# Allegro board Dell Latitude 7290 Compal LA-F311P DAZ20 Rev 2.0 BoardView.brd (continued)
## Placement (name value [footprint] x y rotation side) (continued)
JUSB1  ACON_TCRA2-9U1U93  [ACON_TCRA2-9U1U93_9P-T]  284.36 75.4 270 bottom
JUSB2  ACON_TCRA2-9U1U93  [ACON_TCRA2-9U1U93_9P-T]  15.83 65.95 90 bottom
JUSBC1  JAE_DX07B024XJ1R1300~D  [JAE_DX07B024XJ1R1300_24P]  7.81 109.9 270 top
JUSH1  CVILU_CF5026FD0RK-05-NH  [CVILU_CF5026FD0RK-05-NH_26P-T]  233.45 59.02 180 bottom
JXDP1  JXT_FP270H-061G1AM  [JXT_FP270H-061G1AM_61P]  103.51 129.83 180 bottom
LA5  BLM15PX600SN1D_2P  [MURAT_BLM15PX600SN1D_2P]  250.45 55.95 180 top
LA6  BLM15PX330SN1D_2P  [MURAT_BLM15PX330SN1D_2P]  279.82 22.74 0 top
LA7  BLM15PX330SN1D_2P  [MURAT_BLM15PX330SN1D_2P]  279.82 24.78 0 top
LA8  BLM15PX330SN1D_2P  [MURAT_BLM15PX330SN1D_2P]  279.82 20.71 0 top
LA9  BLM15PX330SN1D_2P  [MURAT_BLM15PX330SN1D_2P]  279.82 18.68 0 top
LA10  BLM15PX330SN1D_2P  [MURAT_BLM15PX330SN1D_2P]  285 45.79 0 bottom
LA11  BLM15PX330SN1D_2P  [MURAT_BLM15PX330SN1D_2P]  285 44.59 0 bottom
LA12  BLM15PX600SN1D_2P  [MURAT_BLM15PX600SN1D_2P]  254.15 66.39 90 top
LA13  HCB2012VF-601T20_2P  [TAI-T_HCB2012KF-121T50_2P]  263.36 63 90 top
LA14  BLM15PX600SN1D_2P  [MURAT_BLM15PX600SN1D_2P]  261.71 65.56 90 top
LC1  BLM15GA750SN1D_2P  [MURAT_BLM15GA750SN1D_2P]  138.07 98.37 270 top
LC2  BLM15GA750SN1D_2P  [MURAT_BLM15GA750SN1D_2P]  129.18 122.43 270 bottom
LED3  LTW-C193DC-C_WHITE  [LED_LTW-C193DC-C_2P]  292.97 128.5 0 top
LI3  EXC24CQ900U_4P  [PANAS_EXC24CQ900U_4P]  23.54 61.94 180 bottom
LI7  EXC24CQ900U_4P  [PANAS_EXC24CQ900U_4P]  277.47 74.26 270 bottom
LI8  MCM1012B900F06BP_4P  [INPAQ_MCM1012B900F06BP_4P]  234.63 106.37 180 top
LI9  MCM1012B900F06BP_4P  [INPAQ_MCM1012B900F06BP_4P]  228.75 78.5 0 bottom
LI16  HCM1012GH900BP_4P  [INPAQ_HCM1012GH900BP_4P]  234.62 104.46 180 top
LI17  HCM1012GH900BP_4P  [INPAQ_HCM1012GH900BP_4P]  230.08 100.59 90 top
LL1  4.7UH +-20% MPB201210T-4R7M-NA2  [TAIYO_BRC2012T4R7MD_2P]  251.42 125.07 90 bottom
LT1  0.6UH_MND-04ABIR60M-XGL_20%  [MAG_MND-04ABIR60M-XGL_2P]  22.43 108.04 180 bottom
LT2  1UH_LQM18NN1R0K00D_10%  [MURAT_LQM18NN1R0K00D_2P]  35.19 88.91 0 bottom
LV1  BLM15PX221SN1D_2P  [MURAT_BLM15PX221SN1D_2P]  62.52 130.04 270 top
LV3  HCM1012GH900BP_4P  [TAIYO_MCF12102G900-T_4P-NPM]  18.21 77.5 180 bottom
LV6  HCM1012GH900BP_4P  [TAIYO_MCF12102G900-T_4P-NPM]  18.21 79.34 180 bottom
LV9  HCM1012GH900BP_4P  [TAIYO_MCF12102G900-T_4P-NPM]  18.21 83.02 180 bottom
LV12  HCM1012GH900BP_4P  [TAIYO_MCF12102G900-T_4P-NPM]  18.21 81.18 180 bottom
LV27  EXC24CQ900U_4P  [PANAS_EXC24CQ900U_4P]  52.6 121.61 0 top
LV31  12NH_LQG15HN12NJ02D_5%  [MURAT_LQG15HN12NJ02D_2P]  18.04 76.78 180 bottom
LV32  12NH_LQG15HN12NJ02D_5%  [MURAT_LQG15HN12NJ02D_2P]  18.04 77.67 180 bottom
LV33  12NH_LQG15HN12NJ02D_5%  [MURAT_LQG15HN12NJ02D_2P]  18.04 78.62 180 bottom
LV34  12NH_LQG15HN12NJ02D_5%  [MURAT_LQG15HN12NJ02D_2P]  18.04 79.51 180 bottom
LV35  12NH_LQG15HN12NJ02D_5%  [MURAT_LQG15HN12NJ02D_2P]  18.04 82.3 180 bottom
LV36  12NH_LQG15HN12NJ02D_5%  [MURAT_LQG15HN12NJ02D_2P]  18.04 83.19 180 bottom
LV37  12NH_LQG15HN12NJ02D_5%  [MURAT_LQG15HN12NJ02D_2P]  18.04 80.46 180 bottom
LV38  12NH_LQG15HN12NJ02D_5%  [MURAT_LQG15HN12NJ02D_2P]  18.04 81.35 180 bottom
LZ1  EXC24CQ900U_4P  [PANAS_EXC24CQ900U_4P]  56.17 121.28 90 top
NOREF  -  []  82.2 91.4 0 top
NOREF#2  -  []  290.6 26.3 0 top
NOREF#3  -  []  36.98 177.87 0 top
NOREF#4  -  []  82.2 113.55 0 top
NOREF#5  -  []  8.6 74.35 90 top
NOREF#6  -  []  286.4 68.2 0 top
NOREF#7  -  []  296.1 26.3 270 top
NOREF#8  -  []  207.1 64.27 0 top
NOREF#9  -  []  4.6 49.5 90 top
NOREF#10  -  []  279.9 13.95 90 top
NOREF#11  -  []  266.9 71.4 0 top
NOREF#12  -  []  5.55 98.7 90 top
NOREF#13  -  []  87.04 69.76 0 top
NOREF#14  -  []  275.9 102.5 0 top
NOREF#15  -  []  33.93 171.65 0 top
NOREF#16  -  []  5.55 115.6 90 top
NOREF#17  -  []  132.46 1.89 0 top
NOREF#18  -  []  114.83 70.48 0 top
NOREF#19  -  []  142 91.4 0 top
NOREF#20  -  []  278.53 3 0 top
NOREF#21  -  []  142 113.55 0 top
NOREF#22  -  []  103.92 72.82 0 top
NOREF#23  -  []  77.91 77.8 0 top
NOREF#24  -  []  126.11 70.5 180 bottom
NOREF#25  -  []  93.57 80.31 180 bottom
NOREF#26  -  []  125.02 40.97 180 bottom
NOREF#27  -  []  204.68 65.48 180 bottom
NOREF#28  -  []  78 132.55 180 bottom
PBATT1  DEREN_40-42251-01001RHF  [DEREN_40-42251-01001RHF_10P-T]  173.1 57.47 135 bottom
PC1  2200P_0402_50V7K  [C_0402]  167.6 56.77 90 top
PC2  2200P_0402_50V7K  [C_0402]  283.03 8.96 0 top
PC3  1U_0603_25V6K  [C_0603]  285.9 13.16 0 top
PC4  0.022U_0603_50V7K  [C_0603]  46.76 110.88 180 bottom
PC5  1000P_0603_50V7K  [C_0603]  40.98 118.95 270 bottom
PC6  0.022U_0603_50V7K  [C_0603]  48.06 120.36 180 bottom
PC7  0.1U_0603_25V7K  [C_0603]  42.25 118.95 270 bottom
PC8  10U_0805_25V6K  [C_0805]  44.31 114.69 180 bottom
PC9  0.1U_0402_10V7K  [C_0402]  55.19 115.86 0 top
PC10  2.2U 10V M X5R 0402  [C_0402]  63.59 118.24 90 bottom
PC11  1000P 50V K X7R 0603  [C_0603]  63.46 120.15 90 bottom
PC12  82P 50V +-5% NPO 0402  [C_0402]  39.13 57.63 0 top
PC100  100P 50V J NPO 0402  [C_0402]  154.39 73.66 90 top
PC102  0.1U_0603_25V7K  [C_0603]  157.52 71.57 90 bottom
PC103  100P 50V J NPO 0402  [C_0402]  153.37 73.42 180 top
PC104  10U_0603_25V6M  [C_0603]  153.06 72.09 180 bottom
PC105  10U_0603_25V6M  [C_0603]  153.06 72.09 180 top
PC106  22UF_0805_6.3V6M  [C_0805]  167.07 76.34 0 bottom
PC107  22UF_0805_6.3V6M  [C_0805]  167.07 76.34 0 top
PC108  22UF_0805_6.3V6M  [C_0805]  167.07 74.56 0 top
PC109  22UF_0805_6.3V6M  [C_0805]  167.07 74.56 0 bottom
PC110  22UF_0805_6.3V6M  [C_0805]  167.07 78.05 0 top
PC111  4.7U_0603_6.3V6K  [C_0603]  156.42 79.03 180 top
PC112  680P_0603_50V7K  [C_0603]  162.72 70.58 90 bottom
PC113  1000P_0402_50V7K  [C_0402]  154.75 78.86 90 bottom
PC114  0.1U_0603_25V7K  [C_0603]  187.6 50.87 90 bottom
PC115  0.1U_0402_25V6  [C_0402]  179 50.53 180 bottom
PC116  2200P_0402_50V7K  [C_0402]  178.31 51.5 180 bottom
PC117  10U_0805_25V6K  [C_0805]  179.93 51.77 90 top
PC118  10U_0805_25V6K  [C_0805]  179.93 51.77 90 bottom
PC119  4.7U_0603_6.3V6K  [C_0603]  186.14 57.22 0 top
PC120  22UF_0805_6.3V6M  [C_0805]  198.09 59.62 0 bottom
PC121  22UF_0805_6.3V6M  [C_0805]  197.76 52.74 270 top
PC122  22UF_0805_6.3V6M  [C_0805]  199.48 52.74 270 bottom
PC123  22UF_0805_6.3V6M  [C_0805]  197.76 52.74 270 bottom
PC124  22UF_0805_6.3V6M  [C_0805]  198.09 59.62 0 top
PC125  680P_0603_50V7K  [C_0603]  190.14 56.02 180 top
PC126  4.7U_0603_6.3V6K  [C_0603]  185.13 57.22 180 top
PC127  1000P_0402_50V7K  [C_0402]  184.86 58.93 90 bottom
PC128  4.7U_0603_6.3V6K  [C_0603]  153.71 78.8 90 bottom
PC129  22UF_0805_6.3V6M  [C_0805]  167.07 78.05 0 bottom
PC130  22UF_0805_6.3V6M  [C_0805]  199.48 52.74 270 top
PC133  1000P_0402_50V7K  [C_0402]  183.27 50.7 90 top
PC134  1000P_0402_50V7K  [C_0402]  178.62 50.77 270 top
PC135  1U_0402_25V6K  [C_0402]  179.53 50.77 270 top
PC136  1U_0402_25V6K  [C_0402]  149.5 71.13 0 bottom
PC137  1000P_0402_50V7K  [C_0402]  165.59 54.52 90 top
PC138  1000P_0402_50V7K  [C_0402]  163.89 51.01 270 top
PC139  1U_0402_25V6K  [C_0402]  162.93 50.99 270 top
PC140  1U_0402_25V6K  [C_0402]  161.9 51 270 top
PC141  100P_0402_50V8J  [C_0402]  168.14 73.19 180 top
PC142  100P_0402_50V8J  [C_0402]  196.15 50.61 90 bottom
PC143  100P_0402_50V8J  [C_0402]  181.24 53.52 270 top
PC200  10U_0805_25V6K  [C_0805]  66.67 74.05 0 top
PC201  10U_0805_25V6K  [C_0805]  66.67 74.05 0 bottom
PC202  100P 50V J NPO 0402  [C_0402]  67.13 75.39 0 bottom
PC203  100P 50V J NPO 0402  [C_0402]  67.13 75.39 0 top
PC204  680P_0603_50V7K  [C_0603]  67.24 70.18 90 top
PC205  0.1U_0603_16V7K  [C_0603]  63.02 67.19 0 bottom
PC206  1U_0402_6.3V6K  [C_0402]  64.49 69.51 180 bottom
PC207  2.2U_0402_6.3V6M  [C_0402]  64.93 69.16 180 top
PC208  330P_0402_50V7K  [C_0402]  63.96 70.81 0 top
PC209  22U_0603_6.3V6M  [C_0603]  70.54 69.23 0 top
PC210  22U_0603_6.3V6M  [C_0603]  68.92 57.41 270 bottom
PC211  22U_0603_6.3V6M  [C_0603]  67.71 57.41 270 bottom
PC212  22U_0603_6.3V6M  [C_0603]  66.5 57.44 270 bottom
PC213  22U_0603_6.3V6M  [C_0603]  68.92 57.41 270 top
PC214  10U_0603_6.3V6M  [C_0603]  67.71 57.41 270 top
PC216  100P 50V J NPO 0402  [C_0402]  70 57.17 270 bottom
PC217  100P_0402_50V8J  [C_0402]  70 57.17 270 top
PC218  1U_0402_10V6K  [C_0402]  70.67 72.53 0 top
PC219  22U_0603_6.3V6M  [C_0603]  70.55 68.01 0 top
PC221  0.1U_0402_10V7K  [C_0402]  70 75 90 top
PC222  0.1U_0402_10V7K  [C_0402]  72.67 75 90 top
PC223  10U_0603_6.3V6M  [C_0603]  66.5 57.44 270 top
PC224  100P_0402_50V8J  [C_0402]  66.22 76.93 270 top
PC301  0.1U_0402_25V6  [C_0402]  151.32 85.69 270 bottom
PC302  680P_0603_50V7K  [C_0603]  154.18 83.49 270 bottom
PC303  100P 50V J NPO 0402  [C_0402]  151.32 85.69 270 top
PC304  0.1U_0603_25V7K  [C_0603]  157.5 87.8 90 top
PC305  10U_0603_25V6M  [C_0603]  152.42 86.21 270 bottom
PC306  10U_0603_25V6M  [C_0603]  152.42 86.21 270 top
PC307  330P_0402_50V7K  [C_0402]  153.21 79.37 0 top
PC308  22U_0603_6.3V6M  [C_0603]  162.5 86.61 0 top
PC309  22U_0603_6.3V6M  [C_0603]  162.5 87.87 0 top
PC310  22U_0603_6.3V6M  [C_0603]  162.5 87.87 0 bottom
PC311  22U_0603_6.3V6M  [C_0603]  162.5 86.61 0 bottom
PC312  4.7U_0603_6.3V6K  [C_0603]  159.27 82.99 0 top
PC313  4.7U_0603_6.3V6K  [C_0603]  159.28 84.31 0 top
PC314  100P_0402_50V8J  [C_0402]  162.43 83.15 0 top
PC315  100P_0402_50V8J  [C_0402]  162.43 84.07 0 top
PC316  100P_0402_50V8J  [C_0402]  159.82 81.79 0 top
PC401  470P_0402_50V7K  [C_0402]  137.44 130.17 90 top
PC402  0.1U_0402_25V6  [C_0402]  142.84 128.14 90 top
PC403  10U_0603_10V6M  [C_0603]  144.68 130.19 90 bottom
PC404  10U_0603_10V6M  [C_0603]  144.68 130.19 90 top
PC406  22U_0603_6.3V6M  [C_0603]  135.85 127.85 0 top
PC407  22U_0603_6.3V6M  [C_0603]  135.85 127.85 0 bottom
PC408  0.1U_0402_25V6  [C_0402]  145.76 130.17 90 top
PC409  2200P_0402_50V7K  [C_0402]  145.76 130.17 90 bottom
PC410  470P_0402_50V7K  [C_0402]  138.15 132.74 90 top
PC411  0.1U_0402_25V6  [C_0402]  163.71 125.74 0 top
PC412  10U_0603_10V6M  [C_0603]  160.62 128.73 90 bottom
PC413  10U_0603_10V6M  [C_0603]  160.62 128.73 90 top
PC415  22U_0603_6.3V6M  [C_0603]  150.67 126.2 180 top
PC417  0.1U_0402_25V6  [C_0402]  161.69 128.65 90 bottom
PC418  2200P_0402_50V7K  [C_0402]  161.69 128.65 90 top
PC419  470P_0402_50V7K  [C_0402]  155.4 127.26 0 top
PC420  470P_0402_50V7K  [C_0402]  160.62 126.83 180 top
PC424  22U_0603_6.3V6M  [C_0603]  150.67 126.2 180 bottom
PC425  10U_0603_6.3V6M  [C_0603]  136.11 126.62 0 top
PC426  10U_0603_6.3V6M  [C_0603]  136.11 126.62 0 bottom
PC427  10U_0603_6.3V6M  [C_0603]  150.67 127.47 180 top
PC428  10U_0603_6.3V6M  [C_0603]  150.67 127.47 180 bottom
PC501  22U_0603_6.3V6M  [C_0603]  177.94 61.78 225 bottom
PC503  68P_0402_50V8J  [C_0402]  173.8 69.16 135 bottom
PC504  22U_0603_6.3V6M  [C_0603]  177.94 61.78 225 top
PC505  0.1U_0402_16V7K  [C_0402]  175.41 66.54 45 bottom
PC506  680P_0402_50V7K  [C_0402]  172.25 62.97 135 bottom
PC513  .1U_0402_16V7K  [C_0402]  150.26 56.58 90 top
PC514  4.7U_0603_6.3V6K  [C_0603]  151.43 62.24 180 top
PC515  0.01UF_0402_25V7K  [C_0402]  146.07 60.86 270 top
PC516  22U_0603_6.3V6M  [C_0603]  148.3 62.03 90 top
PC530  10U_0603_6.3V6M  [C_0603]  169.91 65.43 315 bottom
PC531  10U_0603_6.3V6M  [C_0603]  169.91 65.43 315 top
PC601  680P_0402_50V7K  [C_0402]  50.05 101.69 0 bottom
PC602  0.1U_0402_25V6  [C_0402]  43.38 92.53 180 bottom
PC603  1U_0603_10V6K  [C_0603]  42.73 96.59 180 bottom
PC604  0.22U_0603_25V7K  [C_0603]  42.73 97.8 180 bottom
PC605  47P_0402_50V8J~D  [C_0402]  45.97 94.58 270 bottom
PC606  100U_D_20VM_R55M  [C_D]  52.71 75.82 90 bottom
PC607  100U_D_20VM_R55M  [C_D]  57.17 80.99 0 bottom
PC608  10U 25V 0603 ZRB  [C_0603]  64.48 114.6 90 bottom
PC611  0.22U_0603_16V7K  [C_0603]  60.53 115.09 180 top
PC612  10U 25V 0603 ZRB  [C_0603]  64.48 114.6 90 top
PC613  330P_0402_50V7K  [C_0402]  45.39 92.04 270 bottom
PC614  2200P_0402_50V7K  [C_0402]  48.88 92.49 270 bottom
PC616  33P_0402_50V8J  [C_0402]  47.36 93.37 270 bottom
PC617  1200P_0402_50V7K  [C_0402]  49.15 87.8 270 top
PC618  330P_0402_50V7K  [C_0402]  47.17 89.82 0 bottom
PC619  0.01UF_0402_25V7K  [C_0402]  47.17 88.94 0 bottom
PC620  0.082U_0402_16V7K  [C_0402]  49.15 88.63 90 top
PC621  680P_0402_50V7K  [C_0402]  45.26 87.84 0 top
PC622  680P_0603_50V7K  [C_0603]  67.33 116.09 180 top
PC624  .022U 16V K X7R 0402  [C_0402]  50.92 88.42 90 bottom
PC625  330P_0402_50V7K  [C_0402]  50.67 92.82 90 bottom
PC626  0.047U_0402_25V7K  [C_0402]  50.03 88.42 90 bottom
PC627  2200P_0402_50V7K  [C_0402]  50.03 88.83 90 top
PC628  33P 50V J NPO 0402  [C_0402]  48 97.24 270 bottom
PC629  2200P_0402_50V7K  [C_0402]  50.62 96.35 0 bottom
PC630  2200P_0402_50V7K  [C_0402]  52.04 97.27 90 top
PC631  4700P 25V 0402  [C_0402]  46.21 96.34 0 bottom
PC632  1000P_0402_50V7K  [C_0402]  48.11 99.39 180 bottom
PC633  4700P 50V K X7R 0402  [C_0402]  49.14 99.75 180 top
PC635  0.022U_0402_16V7K  [C_0402]  50.97 87.95 0 top
PC636  33P_0402_50V8J  [C_0402]  48.87 94.88 0 bottom
PC637  0.033U 25V K X7R 0402  [C_0402]  49.14 100.62 180 top
PC638  0.022U_0402_16V7K  [C_0402]  51.98 91.01 90 bottom
PC639  1500P_0402_50V7K  [C_0402]  53.38 94.56 0 top
PC640  2200P_0402_50V7K  [C_0402]  51.65 100.51 0 bottom
PC641  .1U_0402_16V7K  [C_0402]  51.03 90.19 180 bottom
PC642  .022U 16V K X7R 0402  [C_0402]  53.27 97.24 180 bottom
PC643  330P_0402_50V7K  [C_0402]  49.78 97.24 270 bottom
PC644  .1U_0402_16V7K  [C_0402]  47.36 100.68 270 top
PC645  .1U_0402_16V7K  [C_0402]  51.54 97.24 180 bottom
PC646  0.047U_0402_25V7K  [C_0402]  52.47 98.14 180 bottom
PC647  680P_0402_50V7K  [C_0402]  55.17 94.58 270 top
PC649  0.01UF_0402_25V7K  [C_0402]  50.89 99.58 180 top
PC650  0.082U_0402_16V7K  [C_0402]  51.74 100.51 270 top
PC651  330P_0402_50V7K  [C_0402]  54.52 95.49 180 top
PC652  330P_0402_50V7K  [C_0402]  50.89 100.47 180 top
PC653  0.082U_0402_16V7K  [C_0402]  52.76 95.47 90 top
PC654  0.01UF_0402_25V7K  [C_0402]  54.52 96.38 180 top
PC655  0.22U_0603_16V7K  [C_0603]  55.47 103.44 90 bottom
PC656  10U 25V 0603 ZRB  [C_0603]  53.2 107.71 90 top
PC657  10U 25V 0603 ZRB  [C_0603]  54.2 106.55 180 top
PC658  10U 25V 0603 ZRB  [C_0603]  53.2 107.71 90 bottom
PC659  0.1U_0402_25V6K~D  [C_0402]  56.4 103.97 0 top
PC660  2200P_0402_50V7K  [C_0402]  56.4 104.86 0 top
PC661  1U_0402_10V6K  [C_0402]  61.53 107.58 90 bottom
PC662  680P_0603_50V7K  [C_0603]  58.39 111.01 180 top
PC663  0.22U_0603_16V7K  [C_0603]  55.6 84.03 90 bottom
PC664  10U 25V 0603 ZRB  [C_0603]  54.19 87.39 180 top
PC665  10U 25V 0603 ZRB  [C_0603]  54.19 86.18 180 top
PC668  1U_0402_10V6K  [C_0402]  61.59 88.53 90 bottom
PC669  1U_0402_10V6K  [C_0402]  59.17 85.32 180 bottom
PC670  680P_0603_50V7K  [C_0603]  61.97 86.14 180 top
PC671  0.22U_0603_16V7K  [C_0603]  53.83 100.24 0 bottom
PC672  10U 25V 0603 ZRB  [C_0603]  57.91 102.69 0 bottom
PC673  10U 25V 0603 ZRB  [C_0603]  57.91 101.43 0 top
PC674  10U 25V 0603 ZRB  [C_0603]  54.19 86.18 180 bottom
PC675  10U 25V 0603 ZRB  [C_0603]  54.19 87.39 180 bottom
PC676  1U_0402_10V6K  [C_0402]  58.64 104.63 180 bottom
PC677  1U_0402_10V6K  [C_0402]  55.08 96.84 90 bottom
PC678  680P_0603_50V7K  [C_0603]  63.13 95.12 180 top
PC679  0.1U 25V K X5R 0402  [C_0402]  57.03 101.22 180 bottom
PC680  0.1U 25V K X5R 0402  [C_0402]  54.24 107.67 90 bottom
PC681  0.1U 25V K X5R 0402  [C_0402]  54.19 88.39 90 bottom
PC682  10U 25V 0603 ZRB  [C_0603]  54.2 106.55 180 bottom
PC683  10U 25V 0603 ZRB  [C_0603]  57.91 101.43 0 bottom
PC684  10U 25V 0603 ZRB  [C_0603]  57.91 102.69 0 top
PC685  1U_0402_10V6K  [C_0402]  62.37 114.95 180 top
PC689  1000P_0402_50V7K  [C_0402]  62.15 61.21 0 top
PC690  1000P_0402_50V7K  [C_0402]  58.43 70.04 180 bottom
PC691  1U_0402_25V6K  [C_0402]  68.19 81.55 180 bottom
PC692  1U_0402_25V6K  [C_0402]  150.95 79.07 0 bottom
PC695  100P_0402_50V8J  [C_0402]  77.48 119.84 270 bottom
PC696  100P_0402_50V8J  [C_0402]  68.65 110.05 0 top
PC697  1U_0402_10V6K  [C_0402]  58.34 93.81 0 bottom
PC700  12P 50V J NPO 0402  [C_0402]  61.17 104.33 180 top
PC701  68P 50V J NPO 0402  [C_0402]  61.14 105.23 180 top
PC702  100P_0402_50V8J  [C_0402]  60.8 101.23 0 bottom
PC703  100P_0402_50V8J  [C_0402]  72.85 89.63 270 bottom
PC902  0.1U_0402_25V6  [C_0402]  48 79.1 0 top
PC903  2200P_0402_50V7K  [C_0402]  48 79.1 0 bottom
PC904  10U 25V K X6S 0805  [C_0805]  46.21 77.35 180 bottom
PC905  10U 25V K X6S 0805  [C_0805]  46.21 79.07 180 bottom
PC906  10U 25V K X6S 0805  [C_0805]  46.21 79.07 180 top
PC909  15U_B2_25VM_R100M  [C_B2]  46.75 74.76 0 bottom
PC911  10U 25V K X6S 0805  [C_0805]  46.21 77.35 180 top
PC913  10U_0805_25V6K  [C_0805]  58.95 76.3 180 bottom
PC914  10U_0805_25V6K  [C_0805]  58.94 74.6 180 top
PC915  10U_0805_25V6K  [C_0805]  58.95 76.3 180 top
PC916  10U_0805_25V6K  [C_0805]  58.94 74.6 180 bottom
PC921  15U_B2_25VM_R100M  [C_B2]  58.16 72.09 0 bottom
PC925  4.7U 6.3V M X5R 0402  [C_0402]  55.71 61.02 90 bottom
PC926  1U 25V K X5R 0402  [C_0402]  55.51 59.68 270 bottom
PC927  1U 25V K X5R 0402  [C_0402]  56.45 59.12 0 bottom
PC928  0.1U_0402_25V6  [C_0402]  58.89 77.6 180 top
PC929  2200P_0402_50V7K  [C_0402]  58.89 77.6 180 bottom
PC930  0.22U_0603_25V7K  [C_0603]  58.25 62.62 270 top
PC931  1U_0603_25V6  [C_0603]  54.44 58.3 90 bottom
PC932  1U_0402_6.3V6K  [C_0402]  58.76 57.91 90 bottom
PC933  1U_0402_6.3V6K  [C_0402]  53.85 57.34 0 bottom
PC934  0.22U_0603_25V7K  [C_0603]  62.19 56.84 180 top
PC935  10U_0805_25V6K  [C_0805]  176.14 51.79 270 bottom
PC936  10U_0805_25V6K  [C_0805]  176.14 51.79 270 top
PC937  4700P_0402_25V7K  [C_0402]  59.27 52.07 90 top
PC938  10P_0402_50V8J  [C_0402]  53.85 54.67 0 bottom
PC939  0.1U_0402_25V6  [C_0402]  59.18 57.03 180 bottom
PC940  680P_0603_50V7K  [C_0603]  40.54 70.18 90 top
PC941  680P_0603_50V7K  [C_0603]  52.41 65.1 90 top
PC942  1U 25V K X5R 0402  [C_0402]  59.16 56.14 180 bottom
PC943  560P_0402_50V7K  [C_0402]  56.12 54.35 90 bottom
PC944  0.01UF 25V K X7R 0402  [C_0402]  54.75 52.14 0 bottom
PC945  1U 25V K X5R 0402  [C_0402]  60.48 54.93 90 bottom
PC946  0.22U 25V K X5R 0402  [C_0402]  58.95 54.35 90 bottom
PC947  0.1U_0402_25V6  [C_0402]  57.01 54.35 90 bottom
PC949  0.1U_0402_10V7K  [C_0402]  45.19 56.46 180 bottom
PC950  0.1U_0402_25V6  [C_0402]  58.06 55.27 270 bottom
PC951  10U_0805_25VAK  [C_0805]  47.45 77.81 0 bottom
PC952  10U_0805_25VAK  [C_0805]  47.45 77.81 0 top
PC955  0.1U 25V K X5R 0402  [C_0402]  50.53 63.03 0 top
PC956  1000P_0402_50V7K  [C_0402]  62.27 63.12 0 top
PC957  1000P_0402_50V7K  [C_0402]  62.25 62.23 0 top
PC958  1U_0402_25V6K  [C_0402]  62.28 63.99 0 top
PC959  1U_0402_25V6K  [C_0402]  62.27 64.88 0 top
PC960  100P_0402_50V8J  [C_0402]  64.06 60.64 0 top
PC961  100P_0402_50V8J  [C_0402]  64.03 58.72 0 top
PC962  100P_0402_50V8J  [C_0402]  64.07 59.7 0 top
PC1001  22U_0603_6.3V6M  [C_0603]  111.34 101.88 270 top
PC1002  22U_0603_6.3V6M  [C_0603]  108.93 101.89 270 top
PC1003  22U_0603_6.3V6M  [C_0603]  107.75 104.24 270 top
PC1004  22U_0603_6.3V6M  [C_0603]  112.53 101.86 270 top
PC1005  22U_0603_6.3V6M  [C_0603]  73.81 110.82 90 bottom
PC1006  22U_0603_6.3V6M  [C_0603]  83.01 105.92 270 bottom
PC1007  22U_0603_6.3V6M  [C_0603]  110.15 106.59 270 top
PC1008  22U_0603_6.3V6M  [C_0603]  73.81 110.82 90 top
PC1009  22U_0603_6.3V6M  [C_0603]  83.02 108.6 270 bottom
PC1010  22U_0603_6.3V6M  [C_0603]  81.81 108.6 270 bottom
PC1011  22U_0603_6.3V6M  [C_0603]  87.84 105.74 270 top
PC1012  22U_0603_6.3V6M  [C_0603]  75.02 110.83 90 top
PC1013  22U_0603_6.3V6M  [C_0603]  84.22 105.74 270 top
PC1014  22U_0603_6.3V6M  [C_0603]  98.9 106.85 270 top
PC1015  22U_0603_6.3V6M  [C_0603]  100.14 106.84 270 top
PC1016  22U_0603_6.3V6M  [C_0603]  86.7 103.56 270 bottom
PC1017  22U_0603_6.3V6M  [C_0603]  84.21 103.54 270 bottom
PC1018  22U_0603_6.3V6M  [C_0603]  81.78 103.29 270 bottom
PC1019  22U_0603_6.3V6M  [C_0603]  99.03 104.5 270 top
PC1020  22U_0603_6.3V6M  [C_0603]  100.25 104.5 270 top
PC1021  22U_0603_6.3V6M  [C_0603]  82.99 103.28 270 bottom
PC1022  22U_0603_6.3V6M  [C_0603]  85.5 103.55 270 bottom
PC1023  22U_0603_6.3V6M  [C_0603]  81.77 100.53 270 bottom
PC1024  22U_0603_6.3V6M  [C_0603]  83.01 100.52 270 bottom
PC1025  22U_0603_6.3V6M  [C_0603]  98.9 102.07 270 top
PC1026  22U_0603_6.3V6M  [C_0603]  100.09 102.07 270 top
PC1027  22U_0603_6.3V6M  [C_0603]  84.29 102.18 270 top
PC1028  22U_0603_6.3V6M  [C_0603]  84.29 99.39 270 top
PC1029  22U_0603_6.3V6M  [C_0603]  90.17 95.56 90 top
PC1030  1U_0201_6.3V6M  [C_0201]  113.88 106.09 0 top
PC1031  1U_0201_6.3V6M  [C_0201]  106.84 105.19 180 top
PC1032  1U_0201_6.3V6M  [C_0201]  113.88 102.59 0 top
PC1033  1U_0201_6.3V6M  [C_0201]  113.88 103.17 0 top
PC1034  1U_0201_6.3V6M  [C_0201]  113.88 103.76 0 top
PC1035  1U_0201_6.3V6M  [C_0201]  113.88 104.34 0 top
PC1036  1U_0201_6.3V6M  [C_0201]  113.88 104.93 0 top
PC1037  1U_0201_6.3V6M  [C_0201]  113.88 105.51 0 top
PC1038  1U_0201_6.3V6M  [C_0201]  106.83 102.4 180 top
PC1039  1U_0201_6.3V6M  [C_0201]  106.84 104.63 180 top
PC1040  1U_0201_6.3V6M  [C_0201]  98.54 109 0 top
PC1041  1U_0201_6.3V6M  [C_0201]  97.81 108.56 90 top
PC1042  1U_0201_6.3V6M  [C_0201]  101.51 108.88 180 top
PC1043  1U_0201_6.3V6M  [C_0201]  92.19 104.66 90 top
PC1044  1U_0201_6.3V6M  [C_0201]  92.19 102.84 90 top
PC1045  1U_0201_6.3V6M  [C_0201]  91.46 101.92 90 top
PC1046  1U_0201_6.3V6M  [C_0201]  96.04 106.52 90 top
PC1047  1U_0201_6.3V6M  [C_0201]  93.43 104.62 90 top
PC1048  1U_0201_6.3V6M  [C_0201]  93.52 103.52 270 top
PC1049  1U_0201_6.3V6M  [C_0201]  101.4 97.2 90 top
PC1050  1U_0201_6.3V6M  [C_0201]  114.49 109.09 180 top
PC1051  1U_0201_6.3V6M  [C_0201]  112.7 108.98 0 top
PC1052  1U_0201_6.3V6M  [C_0201]  110.87 108.98 180 top
PC1053  1U_0201_6.3V6M  [C_0201]  109.08 108.98 0 top
PC1055  1U_0201_6.3V6M  [C_0201]  93.19 101.41 0 top
PC1056  1U_0201_6.3V6M  [C_0201]  94.76 106.47 90 top
PC1057  22U_0603_6.3V6M  [C_0603]  118.04 99.81 180 top
PC1058  22U_0603_6.3V6M  [C_0603]  119.01 99.81 0 top
PC1059  22U_0603_6.3V6M  [C_0603]  117.22 107.13 180 top
PC1060  22U_0603_6.3V6M  [C_0603]  117.75 104.63 90 top
PC1061  22U_0603_6.3V6M  [C_0603]  76.22 110.82 90 bottom
PC1062  330U_D3_2VM_R6M  [C_D3]  73.58 107.07 180 top
PC1063  330U_D3_2VM_R6M  [C_D3]  73.3 95.01 270 top
PC1064  22U_0603_6.3V6M  [C_0603]  89.05 105.74 270 top
PC1065  22U_0603_6.3V6M  [C_0603]  90.28 105.74 270 top
PC1066  22U_0603_6.3V6M  [C_0603]  111.34 104.21 270 top
PC1067  22U_0603_6.3V6M  [C_0603]  108.94 106.59 270 top
PC1068  22U_0603_6.3V6M  [C_0603]  110.15 104.24 270 top
PC1069  22U_0603_6.3V6M  [C_0603]  80.61 105.74 270 bottom
PC1070  22U_0603_6.3V6M  [C_0603]  81.81 105.74 270 bottom
PC1071  22U_0603_6.3V6M  [C_0603]  80.61 108.6 270 bottom
PC1072  22U_0603_6.3V6M  [C_0603]  85.43 105.74 270 top
PC1073  22U_0603_6.3V6M  [C_0603]  108.94 104.24 270 top
PC1074  22U_0603_6.3V6M  [C_0603]  75.02 110.83 90 bottom
PC1075  22U_0603_6.3V6M  [C_0603]  86.64 105.74 270 top
PC1076  22U_0603_6.3V6M  [C_0603]  112.53 104.2 270 top
PC1077  22U_0603_6.3V6M  [C_0603]  111.34 106.59 270 top
PC1078  22U_0603_6.3V6M  [C_0603]  107.75 106.58 270 top
PC1079  22U_0603_6.3V6M  [C_0603]  84.21 105.92 270 bottom
PC1080  22U_0603_6.3V6M  [C_0603]  107.73 101.89 270 top
PC1081  22U_0603_6.3V6M  [C_0603]  110.13 101.89 270 top
PC1082  22U_0603_6.3V6M  [C_0603]  112.53 106.59 270 top
PC1083  1U_0201_6.3V6M  [C_0201]  106.83 104.07 180 top
PC1084  1U_0201_6.3V6M  [C_0201]  111.49 108.98 0 top
PC1085  1U_0201_6.3V6M  [C_0201]  111.39 110.12 0 top
PC1086  1U_0201_6.3V6M  [C_0201]  106.83 103.52 180 top
PC1087  1U_0201_6.3V6M  [C_0201]  113.49 97.77 270 top
PC1088  1U_0201_6.3V6M  [C_0201]  113.52 99.08 180 top
PC1089  1U_0201_6.3V6M  [C_0201]  112.89 97.77 270 top
PC1090  1U_0201_6.3V6M  [C_0201]  113.89 106.68 0 top
PC1091  1U_0201_6.3V6M  [C_0201]  113.88 107.27 0 top
PC1092  1U_0201_6.3V6M  [C_0201]  106.83 102.96 180 top
PC1093  1U_0201_6.3V6M  [C_0201]  113.88 102 0 top
PC1094  1U_0201_6.3V6M  [C_0201]  113.88 101.42 0 top
PC1095  1U_0201_6.3V6M  [C_0201]  113.88 100.84 0 top
PC1096  1U_0201_6.3V6M  [C_0201]  113.5 100.26 0 top
PC1097  1U_0201_6.3V6M  [C_0201]  111.68 99.67 0 top
PC1098  1U_0201_6.3V6M  [C_0201]  109.98 99.68 0 top
PC1099  1U_0201_6.3V6M  [C_0201]  106.83 101.28 180 top
PC1127  330U_D2_2.5VM_R9M  [C_D2]  74.51 108.3 270 bottom
PC1128  330U_D2_2.5VM_R9M  [C_D2]  74.51 98.27 270 bottom
PC1129  22U_0603_6.3V6M  [C_0603]  90.32 99.39 270 top
PC1130  22U_0603_6.3V6M  [C_0603]  90.32 102.18 270 top
PC1131  22U_0603_6.3V6M  [C_0603]  89.11 102.18 270 top
PC1132  22U_0603_6.3V6M  [C_0603]  89.11 99.4 270 top
PC1133  22U_0603_6.3V6M  [C_0603]  87.91 102.18 270 top
PC1134  22U_0603_6.3V6M  [C_0603]  87.92 99.41 270 top
PC1135  22U_0603_6.3V6M  [C_0603]  86.7 102.18 270 top
PC1136  22U_0603_6.3V6M  [C_0603]  86.7 99.39 270 top
PC1137  22U_0603_6.3V6M  [C_0603]  85.49 102.18 270 top
PC1138  22U_0603_6.3V6M  [C_0603]  85.49 99.39 270 top
PC1139  22U_0603_6.3V6M  [C_0603]  117.4 103.55 180 top
PC1140  22U_0603_6.3V6M  [C_0603]  116.55 104.66 90 top
PC1141  22U_0603_6.3V6M  [C_0603]  74.38 118.76 90 top
PC1142  22U_0603_6.3V6M  [C_0603]  75.7 118.8 90 bottom
PC1143  22U_0603_6.3V6M  [C_0603]  73.08 118.77 90 top
PC1144  22U_0603_6.3V6M  [C_0603]  74.38 118.76 90 bottom
PC1145  22U_0603_6.3V6M  [C_0603]  75.7 118.8 90 top
PC1146  22U_0603_6.3V6M  [C_0603]  73.08 118.77 90 bottom
PC1147  1U_0201_6.3V6M  [C_0201]  116.31 110.17 180 top
PC1148  1U_0201_6.3V6M  [C_0201]  118.39 107.62 270 top
PC1149  1U_0201_6.3V6M  [C_0201]  115.65 106.14 180 top
PC1150  1U_0201_6.3V6M  [C_0201]  115.65 105.57 180 top
PC1151  1U_0201_6.3V6M  [C_0201]  115.65 105 180 top
PC1152  1U_0201_6.3V6M  [C_0201]  118.48 103.49 0 top
PC1153  1U_0201_6.3V6M  [C_0201]  118.48 102.91 0 top
PC1201  0.01U_0402_25V7K~D  [C_0402]  36.47 58.7 270 bottom
PC1202  0.47U 25V K X7R 0603  [C_0603]  46.84 103.58 270 top
PC1203  1500P_0402_50V7K  [C_0402]  47.39 109.62 270 top
PC1204  0.1U_0402_10V7K  [C_0402]  35.06 63.7 0 bottom
PC1205  100P_0402_50V8J~D  [C_0402]  39.66 53.35 180 top
PC1206  220P_0402_50V8J~D  [C_0402]  40.97 55.13 0 top
PC1207  1200P_0402_50V7K  [C_0402]  41.87 56.92 270 top
PC1208  1000P_0402_50V7K  [C_0402]  22.95 112.98 0 top
PC1210  1500P_0402_50V7K  [C_0402]  31.14 120.93 270 top
PC1211  100P_0402_50V8J  [C_0402]  36.59 55.13 0 top
PC1212  100P_0402_50V8J  [C_0402]  36.59 56.91 0 top
PC1213  1200P_0402_50V7K  [C_0402]  35.14 56.7 90 top
PC1214  0.01UF_0402_25V7K  [C_0402]  28.03 124.2 90 top
PC1216  100P_0402_50V8J  [C_0402]  26.15 112.98 180 top
PC1217  1500P_0402_50V7K  [C_0402]  248.94 97.22 90 top
PC1321  220U_D7_2VM_R4.5M  [C_D7]  68.68 102.28 180 top
PC1322  22U_0603_6.3V6M  [C_0603]  103.96 102.41 0 top
PC1323  22U_0603_6.3V6M  [C_0603]  103.96 103.62 0 top
PC1324  22U_0603_6.3V6M  [C_0603]  103.96 104.81 0 top
PC1325  22U_0603_6.3V6M  [C_0603]  102.74 103.62 180 top
PC1326  22U_0603_6.3V6M  [C_0603]  102.74 102.42 180 top
PC1327  22U_0603_6.3V6M  [C_0603]  102.74 104.82 180 top
PC1328  1U_0201_6.3V6M  [C_0201]  94.09 106.43 90 top
PC1329  1U_0201_6.3V6M  [C_0201]  97.73 106.97 270 top
PC1330  1U_0201_6.3V6M  [C_0201]  104.63 96.15 0 top
PC1331  1U_0201_6.3V6M  [C_0201]  103.53 95.51 180 top
PC1332  1U_0201_6.3V6M  [C_0201]  104.63 95.51 0 top
PC1333  1U_0201_6.3V6M  [C_0201]  103.53 96.13 180 top
PC1334  1U_0201_6.3V6M  [C_0201]  105.27 97.29 0 top
PD1  -  [TVNST52302AB0_SOT523-3]  166.79 64.51 45 top
PD2  -  [TVNST52302AB0_SOT523-3]  165.33 63.05 45 top
PD3  BAS40CW SOT-323  [DB3J315E0L_SMINI3-F2-B3]  285.9 11.88 0 top
PD4  -  [PESD5V0U2BT_SOT23-3]  39.66 127.29 180 top
PD5  S SCH DIO 5A 100V 15UA 0.88V TO227-3  [PDS5100H-13_POWERDI5-3]  51.08 114.14 90 bottom
PD6  -  [DFLS160-7_POWERDI123-2]  45.63 118.34 45 top
PD901  SDMK0340L-7-F_SOD323-2~D  [SDMK0340L-7-F_SOD323-2]  48.91 57.54 180 bottom
PD903  -  [RB520SM-30T2R_EMD2-2]  48.91 59.26 180 bottom
PD904  SDMK0340L-7-F_SOD323-2~D  [SDMK0340L-7-F_SOD323-2]  48.91 60.97 180 bottom
PD905  -  [BAT54CW_SOT323-3]  42.51 57.61 0 bottom
PD906  SMF4L22A SOD123FL-2  [SMF22A-SOD123FL-2-S]  48.17 82.62 0 top
PD1202  S SCH DIO 5A 100V 15UA 0.88V TO227-3  [PDS5100H-13_POWERDI5-3]  49.36 107.63 270 bottom
PD1205  -  [SDMK0340L-7-F_SOD323-2]  35.14 54.25 90 bottom
PD1801  BAT54CW-7-F SOT-323  [BAT54CW_SOT323-3]  37.55 58.3 270 bottom
PH601  470K_0402_5%_B25/50 4700K  [R_0402]  54.71 93.8 0 bottom
PH602  10K_0402_5%_B25/50 4250K  [R_0402]  67.27 103.2 180 bottom
PH603  470K_0402_5%_B25/50 4700K  [R_0402]  49.75 91.08 0 bottom
PH604  10KB_0402_5%  [R_0402]  71.79 119.64 270 bottom
PH605  10K_0402_5%_B25/50 4250K  [R_0402]  68.49 85.73 0 bottom
PJP1  PAD-OPEN1X1M  [JUMP_43X39]  124.03 126.12 0 top
PJP2  PAD-OPEN1X1M  [JUMP_43X39]  120.42 125.41 90 top
PJP3  PAD-OPEN1X3M  [JUMP_43X118]  139.91 122.87 270 bottom
PJP4  PAD-OPEN1X1M  [JUMP_43X39]  146.47 83.13 180 top
PJP5  -  [JUMP_43X79]  22.76 110.37 0 top
PJP6  PAD-OPEN1X1M  [JUMP_43X39]  20.47 107.58 90 top
PJP7  PAD-OPEN1X1M  [JUMP_43X39]  34.3 72.97 0 bottom
PJP8  PAD-OPEN 1X3M  [JUMP_43X118]  24.52 85.9 0 top
PJP13  PAD-OPEN1X1M  [JUMP_43X39]  65.04 127.2 0 top
PJP14  PAD-OPEN1X2M  [JUMP_43X79]  271.76 73.35 0 top
PJP15  PAD-OPEN1X1M  [JUMP_43X39]  247.99 67.4 270 top
PJP16  PAD-OPEN1X1M  [JUMP_43X39]  246.21 60.16 270 top
PJP17  PAD-OPEN1X2M  [JUMP_43X79]  243.17 59.68 270 top
PJP18  PAD-OPEN1X1M  [JUMP_43X39]  245.77 66.48 90 top
PJP19  PAD-OPEN1X1M  [JUMP_43X39]  265.89 57.54 0 top
PJP20  PAD-OPEN1X1M  [JUMP_43X39]  262.37 87.12 90 top
PJP21  PAD-OPEN1X1M  [JUMP_43X39]  259.99 87.12 90 top
PJP22  PAD-OPEN1X1M  [JUMP_43X39]  251.46 76.13 90 top
PJP31  PAD-OPEN1X3M  [JUMP_43X118]  27.65 52.42 90 bottom
PJP35  PAD-OPEN1X1M  [JUMP_43X39]  206.58 56.4 0 top
PJP36  PAD-OPEN1X2M  [JUMP_43X79]  249.39 108.38 270 top
PJP37  PAD-OPEN1X1M  [JUMP_43X39]  248.7 113.36 180 top
PJP38  PAD-OPEN1X1M  [JUMP_43X39]  149.68 65.42 180 top
PJP39  PAD-OPEN1X3M  [JUMP_43X118]  153 65.31 90 top
PJP40  PAD-OPEN1X2M  [JUMP_43X79]  276.1 86.05 180 top
PJP41  PAD-OPEN1X3M  [JUMP_43X118]  276.67 95.9 180 top
PJP42  PAD-OPEN1X1M  [JUMP_43X39]  211.59 51.45 0 top
PJP100  PAD-OPEN 1X2M~D  [JUMP_43X79]  153.12 68.61 90 bottom
PJP101  PAD-OPEN 1X2M~D  [JUMP_43X79]  182.9 50.77 90 bottom
PJP102  -  [JUMP_43X118]  167.84 72.1 270 bottom
PJP103  -  [JUMP_43X118]  198.62 56.03 0 bottom
PJP200  -  [JUMP_43X118]  71.8 58.43 0 top
PJP201  -  [JUMP_43X39]  70.84 65.91 0 top
PJP202  PAD-OPEN 1X2M~D  [JUMP_43X79]  63.48 75.19 0 top
PJP301  PAD-OPEN 1X2M~D  [JUMP_43X79]  150.81 82.09 90 top
PJP302  -  [JUMP_43X118]  159.41 87.35 90 bottom
PJP391  PAD-OPEN1X1M  [JUMP_43X39]  156.44 114.69 180 bottom
PJP401  -  [JUMP_43X79]  133.37 130.1 270 bottom
PJP402  -  [JUMP_43X79]  149.23 124.41 270 bottom
PJP403  PAD-OPEN1X1M  [JUMP_43X39]  145.79 128.53 180 bottom
PJP404  PAD-OPEN1X1M  [JUMP_43X39]  161.82 127.11 180 bottom
PJP501  PAD-OPEN1X1M  [JUMP_43X39]  169.37 68.41 315 bottom
PJP502  PAD-OPEN1X1M  [JUMP_43X39]  178.92 60.86 315 bottom
PJP505  PAD-OPEN1X1M  [JUMP_43X39]  153.9 57.61 180 top
PJP506  PAD-OPEN1X1M  [JUMP_43X39]  146.66 62.81 180 top
PJP601  PAD-OPEN 4X4M  [JUMP_43X118]  62.19 76.04 270 bottom
PJP602  PAD-OPEN 1X2M~D  [JUMP_43X79]  56.02 79.72 180 top
PJP603  PAD-OPEN1X1M  [JUMP_43X39]  64.22 113.31 270 bottom
PJP901  PAD-OPEN 4X4M  [JUMP_43X118-NPM]  46.12 82.69 0 bottom
PJP1202  -  [JUMP_43X118]  29.22 115.45 0 top
PJPDC1  CVILU_CI0805M1HRC-NH  [CVILU_CI0805M1HRC-NH_5P-T]  38 122.55 270 bottom
PL1  FBMJ4516HS720NT_2P  [TAIYO_FBMJ4516HS720NT_2P]  170.91 54.93 90 top
PL2  FBMJ4516HS720NT_2P  [TAIYO_FBMJ4516HS720NT_2P]  173.19 54.93 90 top
PL3  BLM15AG102SN1D_2P  [MURAT_BLM15AG102SN1D_2P]  37.95 123.48 0 top
PL4  FBMJ4516HS720NT_2P  [TAIYO_FBMJ4516HS720NT_2P]  41.23 120.79 0 bottom
PL100  1.5UH +-20% 9A 7X7X3 MOLDING  [CYNTE_PCMC063T-1R5MN_2P]  158.72 75.91 0 bottom
PL101  1.5UH +-20% 9A 7X7X3 MOLDING  [CYNTE_PCMC063T-1R5MN_2P]  189.26 55.25 0 bottom
PL201  1UH +-20% 11A 7X7X3 MOLDING, A.2  [CYNTE_PCMB063T-1R0MS_2P]  67.4 65.91 270 bottom
PL301  0.68UH_7.9A_20%_5X5X3_M  [L_5X5X3_M_2P]  158.34 83.09 0 bottom
PL402  1UH_1277AS-H-1R0N-P2_3.3A_30%  [MAG_MLV-FY12N1R0M-O1L_2P]  138.55 130.76 180 bottom
PL404  1UH_1277AS-H-1R0N-P2_3.3A_30%  [MAG_MLV-FY12N1R0M-O1L_2P]  154.42 127.96 180 bottom
PL405  3A_Z120_40M_0603_2P  [3A_Z120_0603_2P]  145.49 126.76 180 bottom
PL406  3A_Z120_40M_0603_2P  [3A_Z120_0603_2P]  161 125.26 180 bottom
PL501  1UH_1277AS-H-1R0N-P2_3.3A_30%  [MAG_MLV-FY12N1R0M-O1L_2P]  174.57 63.85 315 bottom
PL502  3A_Z120_40M_0603_2P  [3A_Z120_0603_2P]  167.69 67.65 315 bottom
PL602  9A Z80 10M 1812_2P  [9A_Z80_1812_2P-NPM]  62.19 77.51 270 bottom
PL610  0.15UH 20% MMD-06CZER15MEX5L 35A  [L_7X7X3_M]  69.94 107.39 180 bottom
PL612  0.15UH 20% MMD-06CZER15MEX5L 35A  [L_7X7X3_M]  70.05 90.12 180 bottom
PL613  0.15UH 20% MMD-06CZER15MEX5L 35A  [L_7X7X3_M]  70.23 99.01 180 bottom
PL614  0.47UH_MMD05CZR47M_12A_20%  [MAG_MMD05CZR47M_4P]  75.21 115.5 180 bottom
PL901  1UH +-20% 6.6A 5X5X3 MOLDING, A.3  [MAGLA_MMD-05CZ-1R0M-M7L_2P]  48.68 82.74 180 bottom
PL902  2.2UH_PCMB103T-2R2MS_13A_20%  [CYNTE_PCMB103T-2R2MS_2P]  44.21 67.77 0 bottom
PL1201  5A_Z120_25M_0805_2P  [TAI-T_HCB2012KF-121T50_2P]  22.78 116.09 0 top
PL1202  5A_Z120_25M_0805_2P  [TAI-T_HCB2012KF-121T50_2P]  22.79 114.3 0 top
PQ1  -  [DMN65D8LDW-7_SOT363-6]  55.39 112.48 90 top
PQ2  -  [FDV301N-G_SOT23-3]  37.23 122.01 90 top
PQ3  MMST3904-7-F_SOT323~D  [MMST3904-7-F_SOT323-3]  35.46 124.66 0 top
PQ4  EMZB08P03VL 1P EDFN3X3-8  [FDMC6679AZ_MLP8-5]  47.73 112.05 180 bottom
PQ5  AO3409 P-CHANNEL SOT-23  [NTR4502PT1G_SOT23-3]  48.51 113.74 270 top
PQ6  -  [DMN65D8LW-7_SOT323-3]  49.68 120.47 270 bottom
PQ7  -  [DMN65D8LW-7_SOT323-3]  44.03 111.87 90 bottom
PQ8  -  [DMN65D8LW-7_SOT323-3]  59.91 119.76 270 bottom
PQ9  EMZB08P03VL 1P EDFN3X3-8  [FDMC6679AZ_MLP8-5]  45.78 118.76 0 bottom
PQ614  PE642DT 2N PDFN3X3S  [AON7934_DFN3X3A8-10]  68.06 113.58 180 bottom
PQ904  AON6962 2N DFN5X6D-8  [AON6970_DFN5X6D-8-7]  59.88 65.42 90 top
PQ905  AON6962 2N DFN5X6D-8  [AON6992_DFN5X6D-8-7]  47.91 68.77 90 top
PQ906  EMZB08P03V 1P EDFN3X3-8  [AON7409_DFN8-5]  175.31 54.07 0 top
PQ909  -  [DMN65D8LW-7_SOT323-3]  51.2 54.31 0 bottom
PQ1201  -  [DMN65D8LDW-7_SOT363-6]  46.44 106.29 90 top
PQ1202  EMZB08P03V 1P EDFN3X3-8  [FDMC6679AZ_MLP8-5]  51.42 109.55 180 top
PQ1203  AO3409 P-CHANNEL SOT-23  [NTR4502PT1G_SOT23-3]  44.54 105.14 180 bottom
PQ1204  -  [DMN65D8LDW-7_SOT363-6]  40.59 107.01 0 bottom
PQ1205  -  [DMN65D8LW-7_SOT323-3]  40.73 63.7 180 bottom
PQ1206  EMZB08P03V 1P EDFN3X3-8  [FDMC6679AZ_MLP8-5]  30.06 119.05 90 top
PQ1207  DMN65D8LDW-7 2N SOT363-6  [DMN66D0LDW-7_SOT363-6]  44.29 50.48 90 bottom
PQ1208  DMN65D8LDW-7 2N SOT363-6  [DMN66D0LDW-7_SOT363-6]  41.02 50.48 90 bottom
PQ1209  -  [DMN65D8LDW-7_SOT363-6]  30.95 123.57 90 top
PQ1210  DMN65D8LDW-7 2N SOT363-6  [DMN66D0LDW-7_SOT363-6]  52.66 51.78 270 bottom
PQ1211  DMN65D8LDW-7 2N SOT363-6  [DMN66D0LDW-7_SOT363-6]  49.42 51.78 270 bottom
PQ1212  -  [DMN65D8LW-7_SOT323-3]  33.7 58.13 0 bottom
PQ1213  EMZB08P03V 1P EDFN3X3-8  [FDMC6679AZ_MLP8-5]  48.53 105.19 270 top
PQ1214  -  [DMN65D8LDW-7_SOT363-6]  44.42 100.74 270 top
PQ1215  AO3409 P-CHANNEL SOT-23  [NTR4502PT1G_SOT23-3]  46.46 101.71 270 bottom
PQ1216  -  [DMN65D8LW-7_SOT323-3]  59.68 51.32 270 bottom
PR1  100K_0402_5%  [R_0402]  168.17 65.23 315 top
PR2  1K_0402_5%  [R_0402]  283.93 9.9 90 top
PR3  0_0402_5%  [R_0402]  42.31 120.61 270 top
PR4  2.2K_0402_5%  [R_0402]  44.22 120.61 270 top
PR5  33_0402_5%  [R_0402]  43.2 119.7 90 top
PR6  100K_0402_1%  [R_0402]  37.17 125.63 270 top
PR7  10K_0402_1%  [R_0402]  33.39 126.21 270 top
PR8  15K_0402_1%  [R_0402]  37.17 127.4 270 top
PR10  300K +-5% 0402  [R_0402]  52.35 114.96 270 top
PR11  499K +-1% 0402  [R_0402]  46.33 109.8 180 bottom
PR12  1M +-5% 0402  [R_0402]  46.62 121.55 0 bottom
PR13  4.7K_0805_5%  [R_0805]  43.78 118.97 270 bottom
PR14  100K_0402_5%  [R_0402]  44.42 116.03 180 bottom
PR15  100K_0402_5%  [R_0402]  52.35 113.12 270 top
PR16  49.9K +-1% 0402  [R_0402]  44.41 109.79 90 bottom
PR17  100K_0402_5%  [R_0402]  55.19 114.91 0 top
PR18  1M +-5% 0402  [R_0402]  48.4 121.55 0 bottom
PR19  0_0402_5%  [R0402_0OHM]  56.98 114.01 90 top
PR20  0_0402_5%  [R0402_0OHM]  42.07 110.06 180 bottom
PR21  0_0402_5%  [R0402_0OHM]  58.84 121.42 180 bottom
PR22  0_0402_5%  [R0402_0OHM]  58.84 120.53 180 bottom
PR23  0_0402_5%  [R0402_0OHM]  52.73 119.7 90 bottom
PR24  100K_0402_5%  [R_0402]  41.04 111.44 90 bottom
PR25  0_0402_5%  [R0402_0OHM]  54.33 114.91 180 top
PR26  0_0402_5%  [R0402_0OHM]  60.15 118.82 0 top
PR27  100K_0402_5%  [R_0402]  58.84 119.64 180 bottom
PR28  100K_0402_5%  [R_0402]  61.06 119.71 180 top
PR29  0_0402_5%  [R0402_0OHM]  61.8 121.75 180 bottom
PR30  100K_0402_1%  [R_0402]  52.98 121.55 0 bottom
PR100  0_0603_5%  [R0603_0OHM]  156.33 72.51 270 bottom
PR102  499K_0402_1%  [R_0402]  182.92 58.94 180 bottom
PR103  499K_0402_1%  [R_0402]  182.92 59.83 180 bottom
PR104  0_0402_5%  [R0402_0OHM]  157.81 79.77 0 top
PR105  0_0402_5%  [R0402_0OHM]  157.75 78.85 0 top
PR106  4.7 +-5% 1206  [R_1206]  158.78 71.47 0 bottom
PR107  100K_0402_5%  [R_0402]  181.08 57.67 180 bottom
PR108  1K_0402_5%  [R_0402]  155.59 79.57 0 bottom
PR111  0_0603_5%  [R0603_0OHM]  186.4 52.27 270 bottom
PR112  4.7_1206_5%  [R_1206]  188.11 54.37 0 top
PR113  100K_0402_5%  [R_0402]  181.96 57.68 270 bottom
PR114  0_0402_5%  [R0402_0OHM]  183.79 59.84 270 bottom
PR116  1M_0402_1%  [R_0402]  152.67 78.77 90 bottom
PR117  1K_0402_5%  [R_0402]  185.75 59.84 0 bottom
PR119  0_0402_5%  [R0402_0OHM]  179.29 57.68 270 bottom
PR120  0_0402_5%  [R0402_0OHM]  181.08 56.78 180 bottom
PR202  4.7_1206_5%  [R_1206]  67.65 66.37 90 top
PR203  0_0603_5%  [R0603_0OHM]  64.41 68.4 180 bottom
PR204  102K_0402_1%  [R_0402]  63.96 71.7 0 top
PR205  0_0402_5%  [R_0402]  64.48 71.65 270 bottom
PR206  100K_0402_1%  [R_0402]  64.87 72.59 180 top
PR207  0_0402_5%  [R_0402]  63.59 70.74 90 bottom
PR208  0_0402_5%  [R0402_0OHM]  70.9 74.13 180 top
PR209  1M_0402_5%  [R_0402]  70.89 75 90 top
PR210  0_0402_5%  [R0402_0OHM]  72.68 74.13 180 top
PR212  1M_0402_5%  [R_0402]  71.78 75 90 top
PR302  1M_0402_1%  [R_0402]  165.96 84.99 180 top
PR303  4.7_1206_5%  [R_1206]  154.21 87.4 270 bottom
PR304  0_0603_5%  [R0603_0OHM]  158.82 89.22 270 top
PR306  21.5K_0402_1%  [R_0402]  153.35 80.33 0 top
PR307  0_0402_5%  [R_0402]  165.96 82.57 180 top
PR308  1K_0402_5%  [R_0402]  155.19 80.41 90 top
PR310  0_0402_5%  [R_0402]  165.03 83.48 0 top
PR311  31.6K_0402_1%  [R_0402]  156.18 81.33 270 top
PR312  0_0402_5%  [R0402_0OHM]  167.02 85.56 270 top
PR402  0_0402_5%  [R0402_0OHM]  144.68 128.14 90 top
PR403  1M_0402_1%  [R_0402]  143.72 128.14 90 top
PR404  0_0402_5%  [R_0402]  140.36 129.82 270 top
PR405  4.7_0603_5%  [R_0603]  138.52 131.52 270 top
PR406  0_0402_5%  [R0402_0OHM]  164.63 127.52 180 top
PR407  1M_0402_1%  [R_0402]  163.71 126.63 0 top
PR408  0_0402_5%  [R_0402]  156.25 131.07 270 top
PR409  4.7_0603_5%  [R_0603]  154.33 128.66 270 top
PR410  0_0402_5%  [R_0402]  164.63 129.3 180 top
PR411  0_0402_5%  [R_0402]  162.4 126.83 180 top
PR412  0_0402_5%  [R_0402]  137.68 133.36 0 bottom
PR413  10K_0402_1%  [R_0402]  141.2 134.48 0 top
PR414  10K_0402_1%  [R_0402]  143.98 133.75 180 top
PR415  10K_0402_1%  [R_0402]  142.11 133.59 180 top
PR416  10K_0402_1%  [R_0402]  143.08 132.85 0 top
PR417  10K_0402_1%  [R_0402]  161.89 125.93 180 top
PR418  10K_0402_1%  [R_0402]  157.14 131.07 270 top
PR419  10K_0402_1%  [R_0402]  161.48 127.72 0 top
PR420  10K_0402_1%  [R_0402]  158.03 130.15 90 top
PR421  0 +-5% 0402  [R_0402]  139.52 132.66 0 bottom
PR422  0_0402_5%  [R_0402]  140.44 133.55 180 bottom
PR423  0_0402_5%  [R0402_0OHM]  156.37 132.09 180 bottom
PR424  100K_0402_1%  [R_0402]  156.37 131.2 180 bottom
PR425  0_0402_5%  [R0402_0OHM]  140.35 128.03 0 top
PR426  0_0402_5%  [R0402_0OHM]  164.63 128.41 180 top
PR427  0_0402_5%  [R_0402]  139.07 134.45 180 top
PR428  1M_0402_1%  [R_0402]  160.62 127.72 180 top
PR501  20K_0402_1%  [R_0402]  173.17 68.52 135 bottom
PR502  4.7_0603_5%  [R_0603]  173.81 61.23 135 bottom
PR504  0_0402_5%  [R0402_0OHM]  174.8 68.44 225 bottom
PR505  1M_0402_1%  [R_0402]  174.78 67.17 45 bottom
PR506  10K_0402_1%  [R_0402]  172.53 70.41 225 bottom
PR513  0_0402_5%  [R0402_0OHM]  149.38 57.49 270 top
PR514  1M_0402_1%  [R_0402]  151.15 56.58 90 top
PR515  21.5K_0402_1%  [R_0402]  146.96 60.86 270 top
PR516  10.2K_0402_1%  [R_0402]  146.06 59.07 0 top
PR517  100K_0402_5%  [R_0402]  171.44 68.54 135 bottom
PR601  45.3_0402_1%  [R_0402]  43.38 93.42 180 bottom
PR602  0_0402_5%  [R0402_0OHM]  42.99 96.59 180 top
PR603  0_0402_5%  [R0402_0OHM]  42.99 97.48 180 top
PR604  75_0402_1%  [R_0402]  43.38 94.31 180 bottom
PR605  100_0402_1%  [R_0402]  43.38 95.2 180 bottom
PR606  0_0402_5%  [R0402_0OHM]  57.72 114.55 0 bottom
PR608  88.7K_0402_1%  [R_0402]  45.06 95.45 0 bottom
PR610  10K_0402_1%  [R_0402]  45.57 89.8 0 top
PR611  1.87K +-1% 0402  [R_0402]  45.27 97.24 270 bottom
PR612  1.91K_0402_1%  [R_0402]  42.47 92.55 0 top
PR613  90.9K +-1% 0402  [R_0402]  44.55 92.03 270 bottom
PR614  0_0402_5%  [R0402_0OHM]  43.05 90.78 90 top
PR615  0_0402_5%  [R_0402]  51.02 86.69 270 top
PR616  0_0402_5%  [R0402_0OHM]  43.94 90.78 90 top
PR617  4.3K_0402_1%  [R_0402]  48.04 91.58 180 bottom
PR618  49.9_0402_1%  [R_0402]  42.47 93.43 0 top
PR619  2.2_0603_5%  [R_0603]  61.17 112.91 0 top
PR620  0_0402_5%  [R0402_0OHM]  44.63 88.9 90 top
PR621  316_0402_1%  [R_0402]  47.96 87.84 90 top
PR622  1.91K_0402_1%  [R_0402]  48.27 89.8 180 top
PR623  2K_0402_1%  [R_0402]  46.99 87.84 90 top
PR624  3.65K_0603_1%  [R_0603]  71.4 115.71 180 top
PR625  0_0402_5%  [R0402_0OHM]  42.46 94.31 0 top
PR626  10_0402_1%  [R_0402]  42.46 95.17 0 top
PR627  4.7_1206_5%  [R_1206]  68.79 114.5 180 top
PR628  4.99K_0402_1%  [R_0402]  67.33 97.5 270 top
PR629  86.6K +-1% 0402  [R_0402]  48.87 93.42 0 bottom
PR630  2.49K_0402_1%  [R_0402]  47.12 97.23 180 bottom
PR631  27.4K_0402_1%  [R_0402]  46.28 92.04 270 bottom
PR632  1K_0402_1%  [R_0402]  51.82 88.85 180 top
PR633  11K_0402_1%  [R_0402]  66.43 96.58 90 top
PR634  0_0402_5%  [R_0402]  50.11 86.69 270 top
PR635  10K_0402_1%  [R_0402]  53.29 92.77 180 top
PR636  665 +-1% 0402  [R_0402]  48.98 99.38 90 bottom
PR638  374_0402_1%  [R_0402]  51.82 89.74 180 top
PR639  3.09K_0402_1%  [R_0402]  50.67 95.46 270 bottom
PR640  374_0402_1%  [R_0402]  52.93 97.29 0 top
PR641  1K_0402_1%  [R_0402]  47.19 100.28 0 bottom
PR642  2.61K_0402_1%  [R_0402]  70.84 118.73 90 bottom
PR643  11K_0402_1%  [R_0402]  71.16 116.79 180 top
PR644  1K_0402_1%  [R_0402]  52.93 98.18 0 top
PR645  316_0402_1%  [R_0402]  54.3 93.67 180 top
PR646  316_0402_1%  [R_0402]  50.76 99.38 90 bottom
PR647  27.4K_0402_1%  [R_0402]  49.74 91.96 0 bottom
PR648  1.91K_0402_1%  [R_0402]  52.5 94.61 270 top
PR649  1.62K_0402_1%  [R_0402]  51.65 99.62 0 bottom
PR650  2K_0402_1%  [R_0402]  54.11 92.74 0 top
PR651  113K_0402_1%  [R_0402]  48.89 97.24 270 bottom
PR652  2K_0402_1%  [R_0402]  49.87 99.38 90 bottom
PR653  20M_0402_5%  [R_0402]  53.72 96.21 180 bottom
PR656  11K_0402_1%  [R_0402]  63.06 105.11 0 top
PR657  4.42K_0402_1%  [R_0402]  66.71 85.73 0 bottom
PR658  20M_0402_5%  [R_0402]  51.79 89.34 270 bottom
PR659  0_0402_5%  [R0402_0OHM]  61.88 103.03 90 bottom
PR660  3.9 +-1% 0603  [R_0603]  56.72 103.43 90 bottom
PR661  3.65K_0603_1%  [R_0603]  66.7 90.12 270 top
PR662  0_0402_5%  [R0402_0OHM]  53.54 100.02 0 top
PR663  4.7_1206_5%  [R_1206]  57.23 112.64 0 top
PR664  0_0402_5%  [R0402_0OHM]  53.54 100.91 0 top
PR665  3.9 +-1% 0603  [R_0603]  56.87 84.03 90 bottom
PR666  10_0402_1%  [R_0402]  67.73 110.18 180 top
PR667  3.65K_0603_1%  [R_0603]  64.29 110.25 270 top
PR668  100K_0402_1%  [R_0402]  64.02 107.69 270 top
PR669  4.7_1206_5%  [R_1206]  65.87 87.01 180 top
PR670  100K_0402_1%  [R_0402]  64.59 96.48 0 top
PR671  0_0402_5%  [R_0402]  56.41 95.38 90 top
PR672  3.9 +-1% 0603  [R_0603]  53.83 99.02 0 bottom
PR673  10_0402_1%  [R_0402]  69.09 99.27 270 top
PR674  3.65K_0603_1%  [R_0603]  65.3 97.48 90 top
PR675  100K_0402_1%  [R_0402]  64.1 98.04 90 top
PR676  4.7_1206_5%  [R_1206]  62.27 99.16 270 top
PR677  100K_0402_1%  [R_0402]  67.73 111.14 180 top
PR678  100_0402_1%  [R_0402]  45.08 93.66 90 bottom
PR679  0_0402_5%  [R0402_0OHM]  61 116.09 180 top
PR680  1_0603_5%  [R_0603]  60.53 83.88 90 bottom
PR681  10K_0402_1%  [R_0402]  61.56 87.6 270 bottom
PR682  -  [SOLDER_PREFORMS_0603]  106.31 99.75 180 top
PR683  -  [SOLDER_PREFORMS_0603]  101.59 106.5 0 top
PR684  -  [SOLDER_PREFORMS_0603]  106.11 106.5 180 top
PR686  10K_0402_1%  [R_0402]  61.17 106.14 180 top
PR687  0_0402_5%  [R0402_0OHM]  62.71 103.03 90 bottom
PR688  1_0603_5%  [R_0603]  60.92 104.07 180 bottom
PR689  10K_0402_1%  [R_0402]  57.5 93.8 180 bottom
PR691  1_0603_5%  [R_0603]  56.55 98.54 270 top
PR692  0_0402_5%  [R_0402]  52.79 95.29 0 bottom
PR901  0.01_1206_1%  [R_1206_4P-D]  46 80.57 90 top
PR909  2 +-1% 0603  [R_0603]  53.16 60.81 0 bottom
PR910  2 +-1% 0603  [R_0603]  53.17 62.01 0 bottom
PR914  0_0603_5%  [R_0603]  57.05 62.62 270 top
PR915  4.7 +-5% 0603  [R_0603]  60.91 59.26 0 top
PR916  1_0805_5%~D  [R_0805]  53.26 59.36 180 bottom
PR917  0.005_1206_1%  [R_1206_4P-D]  170.08 52.03 0 top
PR918  100K_0402_1%  [R_0402]  52.98 56.58 90 bottom
PR919  0_0402_5%  [R_0402]  50.56 58.37 0 top
PR920  0_0402_5%  [R0402_0OHM]  50.56 57.48 0 top
PR921  2.2_0603_5%  [R_0603]  60.79 58.05 0 top
PR922  0_0402_5%  [R0402_0OHM]  50.56 56.59 0 top
PR923  4.7_1206_5%  [R_1206]  43.6 66.08 180 top
PR924  4.7_1206_5%  [R_1206]  55.71 63.57 180 top
PR925  154K_0402_1%  [R_0402]  53.85 56.45 0 bottom
PR926  0_0402_5%  [R0402_0OHM]  50.56 55.7 0 top
PR927  1M_0402_1%  [R_0402]  50.81 57.29 0 bottom
PR928  0_0402_5%  [R0402_0OHM]  52.98 55.71 270 bottom
PR929  0_0402_5%  [R0402_0OHM]  60.79 56.96 45 bottom
PR930  100K_0402_1%  [R_0402]  53.85 55.56 0 bottom
PR931  100K_0402_1%  [R_0402]  53.94 52.07 90 top
PR932  105K +-1% 0402  [R_0402]  55.71 52.98 270 top
PR933  100K_0402_1%  [R_0402]  54.82 52.07 90 top
PR934  499 +-1% 0402  [R_0402]  55.66 53.03 180 bottom
PR935  0_0402_5%  [R0402_0OHM]  56.59 50.75 0 top
PR936  0_0402_5%  [R0402_0OHM]  57.49 52.98 270 top
PR937  1 +-1% 0603  [R_0603]  61.75 56.21 0 bottom
PR938  1 +-1% 0603  [R_0603]  61.43 54.94 0 bottom
PR939  0_0402_5%  [R0402_0OHM]  44.22 58.61 90 bottom
PR940  100_0402_1%  [R_0402]  58.38 52.07 90 top
PR941  0_0402_5%  [R0402_0OHM]  40.73 58.48 90 bottom
PR942  0_0402_5%  [R0402_0OHM]  47.29 54.19 90 bottom
PR943  0_0603_5%  [R_0603]  53.11 60.59 0 top
PR944  442K_0402_1%  [R_0402]  51.57 62.16 180 top
PR945  100K_0402_5%  [R_0402]  51.48 61.14 180 top
PR946  0_0402_5%  [R0402_0OHM]  43.27 54.1 90 bottom
PR947  0_0402_5%  [R0402_0OHM]  56.59 52.14 0 bottom
PR948  12.7K +-1% 0402  [R_0402]  57.61 53.03 0 bottom
PR950  0_0402_5%  [R_0402]  45.11 59.52 270 bottom
PR951  0_0402_5%  [R0402_0OHM]  52.91 52.84 0 bottom
PR953  100K_0402_1%  [R_0402]  43.46 56.16 270 top
PR960  0_0402_5%  [R0402_0OHM]  50.56 59.26 0 top
PR961  100K_0402_1%  [R_0402]  47.71 56.01 0 bottom
PR1201  240K_0402_1%  [R_0402]  41.88 53.35 180 top
PR1202  300K +-5% 0402  [R_0402]  44.3 108.91 180 bottom
PR1203  1.8M_0402_1%  [R_0402]  40.98 56.01 90 top
PR1205  499K +-1% 0402  [R_0402]  45.74 103.21 270 top
PR1206  1K_0402_1%  [R_0402]  38.75 56.02 0 top
PR1207  499K +-1% 0402  [R_0402]  48.21 109.62 270 top
PR1208  102K_0402_1%  [R_0402]  38.75 55.13 0 top
PR1209  100K_0402_5%  [R_0402]  42.06 108.93 270 bottom
PR1210  1M_0402_5%  [R_0402]  33.29 54.43 0 top
PR1211  0_0402_5%  [R0402_0OHM]  36.52 62.56 0 top
PR1212  49.9K +-1% 0402  [R_0402]  44.85 102.3 90 top
PR1213  49.9K +-1% 0402  [R_0402]  48.22 107.83 180 top
PR1214  100K_0402_5%  [R_0402]  42.29 103.06 180 bottom
PR1215  0_0402_5%  [R0402_0OHM]  37.76 63.7 180 bottom
PR1216  0_0402_5%  [R0402_0OHM]  35.46 60.21 0 bottom
PR1217  84.5K_0402_1%  [R_0402]  39.66 54.24 180 top
PR1218  0_0402_5%  [R0402_0OHM]  42.29 103.95 180 bottom
PR1219  23.2K +-1% 0402  [R_0402]  40.97 54.24 0 top
PR1220  0_0402_5%  [R0402_0OHM]  42.68 106.94 0 top
PR1221  0_0402_5%  [R0402_0OHM]  41.63 60.65 180 bottom
PR1222  100K_0402_5%  [R_0402]  42.68 107.83 0 top
PR1223  0_0402_5%  [R0402_0OHM]  41.17 108.01 90 bottom
PR1224  100K_0402_5%  [R_0402]  39.79 60.65 180 bottom
PR1225  0_0402_5%  [R0402_0OHM]  38.95 62.51 270 bottom
PR1226  100K_0402_5%  [R_0402]  36.84 64.59 0 bottom
PR1227  100K_0402_5%  [R_0402]  27.85 122.44 180 top
PR1228  499K +-1% 0402  [R_0402]  32.03 120.01 90 top
PR1229  49.9K +-1% 0402  [R_0402]  29.69 122.44 180 top
PR1230  100K_0402_5%  [R_0402]  46.19 51.18 90 top
PR1231  100K_0402_5%  [R_0402]  50.06 51.18 90 top
PR1232  100K_0402_5%  [R_0402]  44.73 51.18 90 top
PR1233  100K_0402_5%  [R_0402]  47.08 51.18 90 top
PR1234  100K_0402_5%  [R_0402]  43.84 50.54 90 top
PR1235  100K_0402_5%  [R_0402]  49.16 52.84 0 bottom
PR1236  100K_0402_5%  [R_0402]  30.94 125.99 0 top
PR1237  100K_0402_1%  [R_0402]  37.5 57.8 180 top
PR1238  0_0402_5%  [R0402_0OHM]  35.14 54.93 90 top
PR1239  150K_0402_1%  [R_0402]  37.5 53.35 180 top
PR1240  100K_0402_1%  [R_0402]  34.25 57.62 270 top
PR1241  0_0402_5%  [R0402_0OHM]  44.74 52.84 180 bottom
PR1242  0_0402_5%  [R0402_0OHM]  47.97 52.09 270 top
PR1243  0_0402_5%  [R0402_0OHM]  33.36 56.7 90 top
PR1244  0_0402_5%  [R0402_0OHM]  40.71 52.02 0 top
PR1245  0_0402_5%  [R0402_0OHM]  51.07 52.84 0 bottom
PR1246  100K_0402_1%  [R_0402]  36.59 54.24 0 top
PR1247  100K +-1% 0402  [R_0402]  36.59 56.02 0 top
PR1248  0_0402_5%  [R_0402]  32.41 56.7 90 top
PR1249  10K_0402_5%  [R_0402]  33.29 55.32 0 top
PR1250  0_0402_5%  [R0402_0OHM]  32.41 55.33 270 top
PR1251  300K +-5% 0402  [R_0402]  53.24 102.09 180 top
PR1252  100K_0402_5%  [R_0402]  49.95 101.93 180 top
PR1253  100K_0402_5%  [R_0402]  43.44 99.44 90 top
PR1254  0_0402_5%  [R_0402]  34.25 59.4 270 top
PR1255  150K_0402_1%  [R_0402]  32.87 56.88 0 bottom
PR1257  0_0402_5%  [R0402_0OHM]  47.38 52.84 0 bottom
